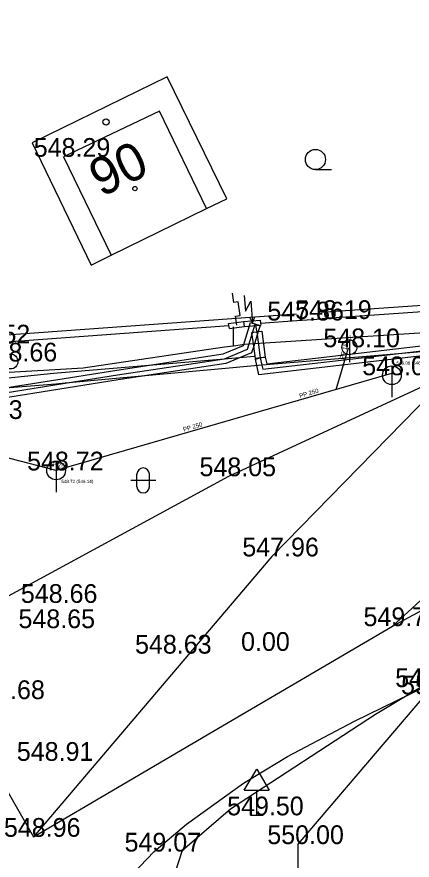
# Model space of a CAD drawing. Extents: x -669995 to -669686, y -1125551 to -1125263.
# Drawn here: x -669832.03 to -669816.2, y -1125420.77 to -1125387.03 of the extents above; entities that cross this region are included whole.
import ezdxf

# ---------------------------------------------------------------- set-up
doc = ezdxf.new("R2010")
doc.units = 0
for name, color, linetype in [('G_Bod_tecka', 7, 'Continuous'), ('G_Bod_vyska', 7, 'Continuous'), ('G_Breh_Teren', 7, 'Continuous'), ('G_Budovy-znacky', 7, 'Continuous'), ('G_Budovy_Objekty', 7, 'Continuous'), ('G_Cesty_Schody', 7, 'Continuous'), ('G_Cisla_orientacni', 7, 'Continuous'), ('G_Objekty_dopravni', 7, 'Continuous'), ('G_Ploty', 7, 'Continuous'), ('G_Ploty_vstupy', 7, 'Continuous'), ('G_Site-kanalizace', 7, 'Continuous'), ('G_Site-Rozvadece', 7, 'Continuous'), ('G_Z_CHRANICKA-TEPLOVOD_kotovane', 7, 'Continuous'), ('G_Z_ELsilove_podz_kotovane', 7, 'Continuous'), ('G_Z_ELsilove_zrusene', 7, 'Continuous'), ('G_Z_KANAL_podz_kotovane', 7, 'Continuous'), ('G_Z_PLYNY_podz_geodeticky', 7, 'Continuous'), ('G_Zelen-okraj', 7, 'Continuous'), ('G_Zelen-Znacky', 7, 'Continuous'), ('Vrstva 11', 7, 'Continuous'), ('Vrstva 2', 7, 'Continuous'), ('Vrstva 3', 7, 'Continuous'), ('Vrstva 8', 7, 'Continuous')]:
    doc.layers.add(name, color=color, linetype=linetype)

msp = doc.modelspace()

# ---------------------------------------------------------------- linework, layer by layer
at = {"layer": 'G_Bod_tecka'}
for p, q in [((-669830.19, -1125392.63), (-669830.19, -1125392.63)), ((-669820.82, -1125399.18), (-669820.82, -1125399.18)), ((-669819.86, -1125399.12), (-669819.86, -1125399.12)), ((-669818.71, -1125400.25), (-669818.71, -1125400.25)), ((-669817.01, -1125401.37), (-669817.01, -1125401.37)), ((-669830.46, -1125405.18), (-669830.46, -1125405.18)), ((-669823.54, -1125405.41), (-669823.54, -1125405.41)), ((-669821.82, -1125408.62), (-669821.82, -1125408.62)), ((-669830.68, -1125410.48), (-669830.68, -1125410.48)), ((-669816.98, -1125411.41), (-669816.98, -1125411.41)), ((-669830.79, -1125411.49), (-669830.79, -1125411.49)), ((-669822.27, -1125412.4), (-669822.27, -1125412.4)), ((-669826.12, -1125412.51), (-669826.12, -1125412.51)), ((-669830.93, -1125416.8), (-669830.93, -1125416.8)), ((-669822.42, -1125418.98), (-669822.42, -1125418.98)), ((-669831.37, -1125419.84), (-669831.37, -1125419.84)), ((-669820.77, -1125420.13), (-669820.77, -1125420.13)), ((-669826.53, -1125420.43), (-669826.53, -1125420.43))]:
    msp.add_line(p, q, dxfattribs=at)
at = {"layer": 'G_Breh_Teren'}
for p, q in [((-669814.65, -1125401.3), (-669821.82, -1125408.62)), ((-669816.98, -1125411.41), (-669810.34, -1125405.31)), ((-669821.82, -1125408.62), (-669831.37, -1125419.84)), ((-669815.66, -1125414.14), (-669820.77, -1125420.13)), ((-669820.77, -1125420.13), (-669820.79, -1125437.75))]:
    msp.add_line(p, q, dxfattribs=at)
at = {"layer": 'G_Budovy-znacky'}
for centre, radius in [((-669828.46, -1125391.24), 0.125), ((-669827.3, -1125393.9), 0.0875)]:
    msp.add_circle(centre, radius, dxfattribs=at)
at = {"layer": 'G_Budovy_Objekty'}
for p, q in [((-669826.01, -1125389.43), (-669831.42, -1125392.07)), ((-669823.62, -1125394.31), (-669826.01, -1125389.43)), ((-669826.32, -1125390.81), (-669830.16, -1125392.63)), ((-669824.43, -1125394.7), (-669826.32, -1125390.81)), ((-669831.42, -1125392.07), (-669829.06, -1125396.96)), ((-669830.16, -1125392.63), (-669828.25, -1125396.56)), ((-669824.43, -1125394.7), (-669823.62, -1125394.31)), ((-669828.25, -1125396.56), (-669824.43, -1125394.7)), ((-669829.06, -1125396.96), (-669828.25, -1125396.56))]:
    msp.add_line(p, q, dxfattribs=at)
at = {"layer": 'G_Cesty_Schody'}
msp.add_line((-669835.83, -1125412.07), (-669831.37, -1125419.84), dxfattribs=at)
for points in [[(-669831.37, -1125419.84), (-669824.18, -1125415.63), (-669816.98, -1125411.41), (-669814.49, -1125410.06), (-669810.62, -1125408.26), (-669806.64, -1125406.64), (-669804.01, -1125405.78), (-669801.31, -1125405.22), (-669798.68, -1125404.88), (-669794.74, -1125404.59), (-669790.8, -1125404.52), (-669786.26, -1125404.75), (-669779.47, -1125405.34), (-669776.07, -1125405.53), (-669772.67, -1125405.5), (-669762.05, -1125404.98), (-669751.43, -1125404.46)], [(-669827.31, -1125430.89), (-669827.81, -1125427.44), (-669828.32, -1125424), (-669828.27, -1125423.02), (-669828.02, -1125422.32), (-669827.38, -1125421.32), (-669826.53, -1125420.43), (-669825.24, -1125419.34), (-669822.95, -1125417.69), (-669821.19, -1125416.63), (-669818.5, -1125415.21), (-669815.71, -1125413.85), (-669812.14, -1125411.91), (-669809.03, -1125410.3), (-669806.44, -1125409.64), (-669803.17, -1125408.56), (-669800.72, -1125407.98), (-669797.03, -1125407.45), (-669793.32, -1125407.28), (-669785.67, -1125407.31), (-669776.28, -1125408.27), (-669772.35, -1125408.22), (-669761.86, -1125407.64), (-669751.66, -1125407.06)]]:
    msp.add_lwpolyline(points, dxfattribs=at)
at = {"layer": 'G_Objekty_dopravni'}
for p, q in [((-669822.92, -1125417.98), (-669822.42, -1125417.13)), ((-669822.42, -1125417.13), (-669821.92, -1125417.98)), ((-669822.92, -1125417.98), (-669821.92, -1125417.98)), ((-669822.42, -1125418.98), (-669822.42, -1125417.98)), ((-669822.67, -1125418.98), (-669822.17, -1125418.98))]:
    msp.add_line(p, q, dxfattribs=at)
at = {"layer": 'G_Ploty'}
for p, q in [((-669809.72, -1125398.17), (-669819.84, -1125398.86)), ((-669809.7, -1125398.42), (-669819.82, -1125399.11)), ((-669820.84, -1125398.93), (-669833.43, -1125399.84)), ((-669822.27, -1125399.28), (-669820.82, -1125399.18)), ((-669833.41, -1125400.1), (-669823.54, -1125399.38))]:
    msp.add_line(p, q, dxfattribs=at)
at = {"layer": 'G_Ploty_vstupy'}
msp.add_line((-669820.82, -1125399.18), (-669819.82, -1125399.11), dxfattribs=at)
at = {"layer": 'G_Site-kanalizace'}
for p, q in [((-669818.71, -1125399.95), (-669818.71, -1125400.85)), ((-669817.01, -1125400.995), (-669817.01, -1125402.245)), ((-669830.46, -1125404.805), (-669830.46, -1125406.055))]:
    msp.add_line(p, q, dxfattribs=at)
for centre, radius in [((-669818.71, -1125400.25), 0.3), ((-669832.29, -1125400.82), 0.3), ((-669817.01, -1125401.37), 0.375), ((-669830.46, -1125405.18), 0.375)]:
    msp.add_circle(centre, radius, dxfattribs=at)
at = {"layer": 'G_Site-Rozvadece'}
for p, q in [((-669822.925, -1125398.177), (-669822.877, -1125398.801)), ((-669822.877, -1125398.801), (-669822.656, -1125398.408)), ((-669822.656, -1125398.408), (-669822.59, -1125399.28)), ((-669823.55, -1125399.3), (-669822.95, -1125399.22)), ((-669822.95, -1125399.22), (-669822.28, -1125399.17)), ((-669822.95, -1125399.22), (-669822.92, -1125399.42)), ((-669822.718, -1125399.044), (-669822.59, -1125399.28)), ((-669822.59, -1125399.28), (-669822.499, -1125399.028)), ((-669823.52, -1125399.5), (-669822.92, -1125399.42)), ((-669822.92, -1125399.42), (-669822.26, -1125399.37))]:
    msp.add_line(p, q, dxfattribs=at)
for points in [[(-669823.22, -1125399.37), (-669823.268, -1125399.005), (-669823.087, -1125398.981), (-669823.16, -1125398.434), (-669823.341, -1125398.457), (-669823.391, -1125398.092)], [(-669823.52, -1125399.5), (-669823.54, -1125399.38), (-669823.55, -1125399.3)], [(-669822.28, -1125399.17), (-669822.27, -1125399.28), (-669822.26, -1125399.37)]]:
    msp.add_lwpolyline(points, dxfattribs=at)
at = {"layer": 'G_Z_CHRANICKA-TEPLOVOD_kotovane'}
for points in [[(-669839.887, -1125402.08), (-669835.752, -1125402.15), (-669833.78, -1125402.071), (-669828.031, -1125401.162), (-669823.774, -1125400.516), (-669822.953, -1125400.181), (-669822.671, -1125399.261), (-669822.289, -1125399.379), (-669822.364, -1125399.623), (-669822.544, -1125400.211), (-669822.627, -1125400.479), (-669823.666, -1125400.904), (-669827.969, -1125401.558), (-669833.74, -1125402.469), (-669835.748, -1125402.55), (-669839.886, -1125402.48), (-669839.893, -1125402.48), (-669839.89, -1125402.281)], [(-669822.222, -1125399.604), (-669822.083, -1125400.645), (-669822.082, -1125400.654), (-669822.28, -1125400.68), (-669822.478, -1125400.706), (-669822.544, -1125400.211), (-669822.618, -1125399.656), (-669822.364, -1125399.623)], [(-669805.384, -1125399.68), (-669805.379, -1125399.68), (-669805.37, -1125399.88), (-669805.361, -1125400.08), (-669815.454, -1125400.55), (-669822.336, -1125401.35), (-669822.475, -1125400.723), (-669822.28, -1125400.68), (-669822.085, -1125400.637), (-669822.083, -1125400.645), (-669822.024, -1125400.91), (-669815.486, -1125400.151), (-669805.669, -1125399.694)]]:
    msp.add_lwpolyline(points, close=True, dxfattribs=at)
at = {"layer": 'G_Z_ELsilove_podz_kotovane'}
for points in [[(-669849.84, -1125407.98), (-669849.55, -1125407.95), (-669849.27, -1125406.85), (-669847.75, -1125403.54), (-669847.02, -1125402.71), (-669845.992, -1125402.648), (-669843.782, -1125402.515), (-669839.89, -1125402.28), (-669838.345, -1125402.306), (-669836.999, -1125402.329), (-669835.75, -1125402.35), (-669833.76, -1125402.27), (-669830.092, -1125401.691), (-669828, -1125401.36), (-669823.72, -1125400.71), (-669823.718, -1125400.709), (-669822.79, -1125400.33), (-669822.48, -1125399.32)], [(-669822.48, -1125399.32), (-669822.42, -1125399.63), (-669822.28, -1125400.68), (-669822.216, -1125400.97), (-669822.18, -1125401.13), (-669817.058, -1125400.535), (-669815.47, -1125400.35)], [(-669825.82, -1125421.69), (-669825.4, -1125420.37), (-669823.47, -1125418.72), (-669817.66, -1125414.93), (-669810.41, -1125410.58), (-669804, -1125408.54), (-669793.75, -1125407.46), (-669779.34, -1125406.79), (-669768.33, -1125406.35), (-669758.83, -1125405.98), (-669749.3, -1125405.76), (-669740.13, -1125406.68), (-669730.37, -1125408.08), (-669716.63, -1125408.89), (-669706.64, -1125409.51), (-669701.451, -1125408.897)]]:
    msp.add_lwpolyline(points, dxfattribs=at)
at = {"layer": 'G_Z_ELsilove_zrusene'}
for points in [[(-669814.133, -1125400.288), (-669817.058, -1125400.535), (-669822.208, -1125400.969), (-669822.216, -1125400.97), (-669830.092, -1125401.691), (-669830.468, -1125401.725), (-669836.547, -1125402.21), (-669836.999, -1125402.329), (-669839.381, -1125402.956), (-669840.894, -1125403.26), (-669842.624, -1125403.184), (-669845.992, -1125402.648), (-669847.235, -1125402.45), (-669848.469, -1125402.12), (-669850.471, -1125401.585), (-669850.931, -1125400.913), (-669850.742, -1125399.899), (-669849.768, -1125396.834), (-669848.073, -1125391.245), (-669846.736, -1125386.251)], [(-669814.133, -1125400.288), (-669817.058, -1125400.535), (-669822.208, -1125400.969), (-669822.216, -1125400.97), (-669830.092, -1125401.691), (-669830.468, -1125401.725), (-669836.547, -1125402.21), (-669836.999, -1125402.329), (-669839.381, -1125402.956), (-669840.894, -1125403.26), (-669842.624, -1125403.184), (-669845.992, -1125402.648), (-669847.235, -1125402.45), (-669848.469, -1125402.12), (-669850.471, -1125401.585), (-669850.931, -1125400.913), (-669850.742, -1125399.899), (-669849.768, -1125396.834), (-669848.073, -1125391.245), (-669846.736, -1125386.251)], [(-669846.446, -1125386.365), (-669847.762, -1125391.264), (-669849.405, -1125396.935), (-669850.481, -1125399.811), (-669850.655, -1125400.859), (-669850.17, -1125401.432), (-669848.385, -1125401.833), (-669847.104, -1125402.12), (-669843.782, -1125402.515), (-669842.45, -1125402.673), (-669840.932, -1125402.788), (-669839.388, -1125402.551), (-669838.345, -1125402.306), (-669836.654, -1125401.909), (-669830.57, -1125401.283), (-669823.718, -1125400.709), (-669822.529, -1125400.61)], [(-669846.446, -1125386.365), (-669847.762, -1125391.264), (-669849.405, -1125396.935), (-669850.481, -1125399.811), (-669850.655, -1125400.859), (-669850.17, -1125401.432), (-669848.385, -1125401.833), (-669847.104, -1125402.12), (-669843.782, -1125402.515), (-669842.45, -1125402.673), (-669840.932, -1125402.788), (-669839.388, -1125402.551), (-669838.345, -1125402.306), (-669836.654, -1125401.909), (-669830.57, -1125401.283), (-669823.718, -1125400.709), (-669822.529, -1125400.61)]]:
    msp.add_lwpolyline(points, dxfattribs=at)
at = {"layer": 'G_Z_KANAL_podz_kotovane'}
msp.add_line((-669819.24, -1125401.94), (-669818.74, -1125400.27), dxfattribs=at)
msp.add_lwpolyline([(-669817.03, -1125401.3), (-669830.46, -1125405.18), (-669837.07, -1125403.48)], dxfattribs=at)
at = {"layer": 'G_Z_PLYNY_podz_geodeticky'}
for points in [[(-669839.96, -1125401.69), (-669839.65, -1125401.68), (-669829.38, -1125401.08), (-669823.72, -1125400.23), (-669823.35, -1125400.2), (-669822.91, -1125400.13), (-669812.4, -1125399.44), (-669811.498, -1125399.357), (-669810.66, -1125399.28), (-669809.29, -1125399.19), (-669796.31, -1125398.41), (-669789.98, -1125398.03), (-669757.52, -1125395.74), (-669752.71, -1125395.41)], [(-669823.35, -1125400.2), (-669823.36, -1125399.58), (-669823.36, -1125399.43)]]:
    msp.add_lwpolyline(points, dxfattribs=at)
at = {"layer": 'G_Zelen-okraj'}
for p, q in [((-669823.54, -1125405.41), (-669814.65, -1125401.3)), ((-669835.83, -1125412.07), (-669823.54, -1125405.41))]:
    msp.add_line(p, q, dxfattribs=at)
at = {"layer": 'G_Zelen-Znacky'}
for p, q in [((-669820.072, -1125393.14), (-669819.422, -1125393.137)), ((-669827.22, -1125405.83), (-669827.22, -1125405.33)), ((-669826.72, -1125405.83), (-669826.72, -1125405.33)), ((-669826.47, -1125405.58), (-669827.47, -1125405.58))]:
    msp.add_line(p, q, dxfattribs=at)
msp.add_circle((-669820.072, -1125392.737), 0.403, dxfattribs=at)
for centre, start, end in [((-669826.97, -1125405.33), 0, 180), ((-669826.97, -1125405.83), 180, 0)]:
    msp.add_arc(centre, 0.25, start, end, dxfattribs=at)
at = {"layer": 'Vrstva 11'}
msp.add_line((-669819.235, -1125401.937), (-669818.74, -1125400.27), dxfattribs=at)
msp.add_lwpolyline([(-669817.03, -1125401.3), (-669830.46, -1125405.18), (-669837.07, -1125403.48)], dxfattribs=at)
at = {"layer": 'Vrstva 8'}
for p, q in [((-669818.74, -1125400.27), (-669818.74, -1125400.27)), ((-669817.03, -1125401.3), (-669817.03, -1125401.3)), ((-669830.46, -1125405.18), (-669830.46, -1125405.18))]:
    msp.add_line(p, q, dxfattribs=at)

# ---------------------------------------------------------------- texts
at = {"layer": 'G_Bod_vyska'}
for s, p in [('548.29', (-669831.356, -1125392.63)), ('547.86', (-669821.998, -1125399.18)), ('548.19', (-669820.884, -1125399.12)), ('548.52', (-669834.564, -1125400.1)), ('548.10', (-669819.754, -1125400.25)), ('548.66', (-669833.482, -1125400.82)), ('548.08', (-669818.196, -1125401.37)), ('549.03', (-669834.868, -1125403.12)), ('548.72', (-669831.624, -1125405.18)), ('548.05', (-669824.716, -1125405.41)), ('547.96', (-669823, -1125408.62)), ('548.66', (-669831.872, -1125410.48)), ('548.65', (-669831.968, -1125411.49)), ('549.73', (-669818.146, -1125411.41)), ('548.63', (-669827.298, -1125412.51)), ('0.00', (-669823.05, -1125412.4)), ('549.72', (-669816.876, -1125413.85)), ('550.11', (-669816.642, -1125414.14)), ('548.68', (-669833.978, -1125414.33)), ('548.91', (-669832.034, -1125416.8)), ('549.50', (-669823.608, -1125418.98)), ('548.96', (-669832.55, -1125419.84)), ('550.00', (-669821.999, -1125420.13)), ('549.07', (-669827.718, -1125420.43))]:
    msp.add_text(s, height=0.75, dxfattribs=at).set_placement(p)
at = {"layer": 'G_Cisla_orientacni'}
msp.add_text('90', height=1.5, rotation=25.938, dxfattribs=at).set_placement((-669828.654, -1125394.26))
at = {"layer": 'Vrstva 2'}
for s, height, p in [('\xa0()', 0.1316, (-669818.806, -1125399.917)), ('\xa0()', 0.1316, (-669832.085, -1125400.467)), ('548.08 (546.34)', 0.13163, (-669816.824, -1125400.948)), ('548.72 (546.14)', 0.13163, (-669830.254, -1125405.687))]:
    msp.add_text(s, height=height, dxfattribs=at).set_placement(p)
at = {"layer": 'Vrstva 3'}
for s, rotation, p in [('PP 150', 73.4269, (-669818.939, -1125400.756)), ('PP 250', 16.1266, (-669820.692, -1125402.285)), ('PP 250', 16.1152, (-669825.346, -1125403.629)), ('PP 250', 351.8582, (-669830.785, -1125404.986))]:
    msp.add_text(s, height=0.1755, rotation=rotation, dxfattribs=at).set_placement(p)

doc.saveas('drawing.dxf')
